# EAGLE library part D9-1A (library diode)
8 DIODES SIL, common anode
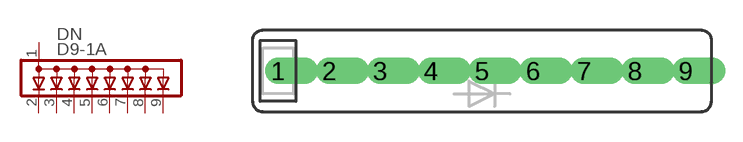
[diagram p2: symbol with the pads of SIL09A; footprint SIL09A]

Designator prefix DN

## D9-1A  [SIL09A]
1  A  pas
2  C2  pas
3  C3  pas
4  C4  pas
5  C5  pas
6  C6  pas
7  C7  pas
8  C8  pas
9  C9  pas

## Footprint SIL09A (pad centres in mm)
8 DIODES single in line 8 diodes with common anode
drill 0.813 offset: 1 -10.16,0; 2 -7.62,0; 3 -5.08,0; 4 -2.54,0; 5 0,0; 6 2.54,0; 7 5.08,0; 8 7.62,0; 9 10.16,0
